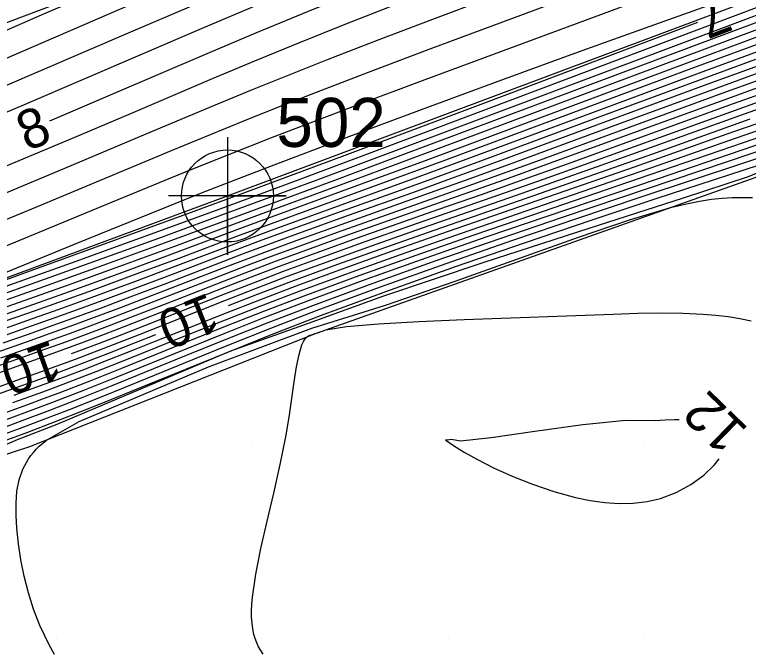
# Model space of a CAD drawing. Extents: x 2602990 to 2605851, y 618069 to 619180.
# Drawn here: x 2603377.87 to 2603415.29, y 618389.19 to 618421.79 of the extents above; entities that cross this region are included whole.
import ezdxf

# ---------------------------------------------------------------- set-up
doc = ezdxf.new("R2010")
doc.units = 0
for name, color, linetype in [('DTM Contours Major', 7, 'Continuous'), ('DTM Contours Major Text', 7, 'Continuous'), ('DTM Contours Minor', 7, 'Continuous'), ('DTM Contours Minor Text', 7, 'Continuous'), ('Exist DTM Breakline', 7, 'Continuous'), ('Exist DTM Crownline', 7, 'Continuous'), ('Exist DTM Drainline', 7, 'Continuous'), ('Exist DTM Drainline Cogo Number', 7, 'Continuous'), ('Exist DTM Drainline Cogo Point CELL', 7, 'Continuous'), ('Exist DTM QL2 LIDAR Elevation Point', 7, 'Continuous'), ('Exist Roads EOP', 7, 'Continuous'), ('PH Exist DTM Breakline', 7, 'Continuous')]:
    doc.layers.add(name, color=color, linetype=linetype)

# ---------------------------------------------------------------- blocks, each defined once
blk = doc.blocks.new('EXIST DTM DRAINLINE COGO POINT')
at = {"layer": 'Exist DTM Drainline Cogo Point CELL'}
blk.add_lwpolyline([(0, 0.06), (0, -0.06), (0, 0), (0.06, 0), (-0.06, 0)], dxfattribs=at)
blk.add_circle((0, 0), 0.04688, dxfattribs=at)

msp = doc.modelspace()

# ---------------------------------------------------------------- linework, layer by layer
at = {"layer": 'DTM Contours Major'}
for points in [[(2603413.545, 618431.919), (2603412.996, 618431.681), (2603409.631, 618430.243), (2603406.411, 618428.892), (2603404.635, 618428.163), (2603402.929, 618427.472), (2603397.939, 618425.471), (2603396.224, 618424.775), (2603393.341, 618423.584), (2603390.362, 618422.333), (2603387.382, 618421.067), (2603378.36, 618417.204), (2603374.888, 618415.735), (2603371.983, 618414.523), (2603369.421, 618413.467), (2603366.184, 618412.15), (2603362.493, 618410.666), (2603360.498, 618409.871), (2603355.313, 618407.823), (2603347.349, 618404.69), (2603343.063, 618402.99), (2603334.617, 618399.609), (2603327.541, 618396.809), (2603322.626, 618394.861)], [(2603377.465, 618406.199), (2603378.885, 618406.7), (2603381.649, 618407.69), (2603384.266, 618408.647), (2603386.257, 618409.391), (2603389.209, 618410.503), (2603390.976, 618411.156), (2603397.03, 618413.357), (2603399.859, 618414.399), (2603412.516, 618419.101), (2603416.414, 618420.536)], [(2603388.785, 618406.968), (2603390.263, 618407.544), (2603392.004, 618408.206), (2603394.355, 618409.072), (2603396.811, 618409.95), (2603399.327, 618410.832), (2603404.362, 618412.578), (2603406.793, 618413.425), (2603410.417, 618414.707), (2603415.392, 618416.478)], [(2603393.201, 618405.543), (2603393.274, 618405.56), (2603393.614, 618405.688), (2603393.745, 618405.726), (2603394.797, 618405.893), (2603396.431, 618406.032), (2603398.488, 618406.149), (2603400.806, 618406.251), (2603408.396, 618406.538), (2603409.666, 618406.576), (2603410.851, 618406.593), (2603411.953, 618406.583), (2603412.976, 618406.538), (2603413.637, 618406.484), (2603414.266, 618406.408), (2603414.867, 618406.31), (2603415.444, 618406.189)], [(2603376.889, 618402.417), (2603377.898, 618402.77), (2603378.871, 618403.116), (2603379.819, 618403.461), (2603380.753, 618403.808), (2603381.684, 618404.16), (2603382.624, 618404.523), (2603384.037, 618405.079), (2603385.068, 618405.49)], [(2603390.549, 618389.192), (2603390.426, 618389.382), (2603390.317, 618389.578), (2603390.223, 618389.781), (2603390.144, 618389.991), (2603390.079, 618390.209), (2603390.019, 618390.487), (2603389.98, 618390.779), (2603389.96, 618391.086), (2603389.957, 618391.408), (2603389.971, 618391.746), (2603390, 618392.102), (2603390.167, 618393.279), (2603390.427, 618394.582), (2603390.746, 618395.973), (2603391.089, 618397.412), (2603391.422, 618398.861), (2603391.71, 618400.279), (2603391.878, 618401.281), (2603392.016, 618402.224), (2603392.138, 618403.086), (2603392.255, 618403.846), (2603392.38, 618404.482), (2603392.528, 618404.972), (2603392.567, 618405.063), (2603392.608, 618405.145), (2603392.652, 618405.218), (2603392.698, 618405.28), (2603392.748, 618405.333), (2603392.801, 618405.375), (2603392.865, 618405.42), (2603392.933, 618405.453), (2603393.072, 618405.499), (2603393.201, 618405.543)]]:
    msp.add_lwpolyline(points, dxfattribs=at)
at = {"layer": 'DTM Contours Minor'}
for points in [[(2603415.971, 618436.239), (2603414.184, 618435.441), (2603412.408, 618434.669), (2603410.673, 618433.922), (2603409.232, 618433.298), (2603401.988, 618430.14), (2603383.339, 618422.102), (2603375.419, 618418.701), (2603372.067, 618417.276), (2603370.458, 618416.602), (2603368.309, 618415.722), (2603367.778, 618415.509)], [(2603403.118, 618431.883), (2603402.833, 618431.716), (2603401.509, 618431.051), (2603400.138, 618430.437), (2603398.705, 618429.837), (2603396.601, 618428.974), (2603389.756, 618426.194), (2603387.413, 618425.235), (2603385.098, 618424.275), (2603383.059, 618423.417), (2603381.096, 618422.58), (2603379.234, 618421.777), (2603375.917, 618420.331), (2603372.342, 618418.768), (2603370.744, 618418.086), (2603369.125, 618417.415), (2603367.476, 618416.749), (2603366.161, 618416.225), (2603363.212, 618415.062), (2603355.846, 618412.179), (2603342.883, 618407.119), (2603323.073, 618399.352)], [(2603420.925, 618431.813), (2603413.975, 618428.875), (2603411.497, 618427.843), (2603408.988, 618426.821), (2603406.566, 618425.862), (2603404.148, 618424.925), (2603399.344, 618423.088), (2603396.97, 618422.174), (2603394.622, 618421.253), (2603392.343, 618420.337), (2603390.114, 618419.421), (2603387.951, 618418.517), (2603383.898, 618416.8), (2603380.805, 618415.486), (2603377.358, 618414.039)], [(2603416.391, 618431.52), (2603413.497, 618430.282), (2603410.574, 618429.047), (2603407.701, 618427.859), (2603405.585, 618427.007), (2603403.524, 618426.193), (2603397.47, 618423.827), (2603395.427, 618423.014), (2603392.846, 618421.963), (2603390.247, 618420.883), (2603387.683, 618419.802), (2603382.87, 618417.749), (2603379.648, 618416.374)], [(2603404.805, 618429.792), (2603402.356, 618428.763), (2603397.015, 618426.54), (2603393.763, 618425.171), (2603390.363, 618423.726), (2603383.658, 618420.855), (2603377.118, 618418.051), (2603373.608, 618416.562), (2603370.947, 618415.449), (2603368.133, 618414.295), (2603365.49, 618413.229), (2603362.398, 618411.996), (2603356.695, 618409.75), (2603347.476, 618406.133), (2603343.027, 618404.375), (2603335.553, 618401.401), (2603324.512, 618397.047), (2603321.717, 618395.941)], [(2603420.115, 618429.811), (2603414.444, 618427.466), (2603412.4, 618426.631), (2603410.273, 618425.78), (2603407.575, 618424.729), (2603404.796, 618423.669), (2603399.182, 618421.553), (2603396.445, 618420.513), (2603393.816, 618419.495), (2603391.861, 618418.719), (2603389.996, 618417.962), (2603388.217, 618417.228), (2603384.894, 618415.834), (2603380.738, 618414.085), (2603376.915, 618412.495), (2603372.47, 618410.663), (2603366.926, 618408.396), (2603360.741, 618405.884), (2603357.67, 618404.644), (2603353.114, 618402.816), (2603345.544, 618399.793), (2603340.999, 618397.957), (2603339.355, 618397.29)], [(2603419.344, 618427.828), (2603414.878, 618426.042), (2603413.257, 618425.399), (2603411.538, 618424.727), (2603408.592, 618423.6), (2603405.452, 618422.42), (2603399.003, 618420.016), (2603395.902, 618418.85), (2603393.023, 618417.746), (2603391.418, 618417.117), (2603389.917, 618416.517), (2603388.501, 618415.943), (2603385.862, 618414.853), (2603379.015, 618412.007), (2603373.646, 618409.794), (2603366.67, 618406.942), (2603359.531, 618404.041), (2603352.87, 618401.348), (2603345.847, 618398.525), (2603340.928, 618396.532), (2603333.274, 618393.41), (2603325.868, 618390.375), (2603313.612, 618385.304)], [(2603417.517, 618425.453), (2603414.066, 618424.14), (2603412.789, 618423.658), (2603409.595, 618422.466), (2603398.796, 618418.475), (2603395.337, 618417.183), (2603392.219, 618416), (2603391, 618415.528), (2603388.789, 618414.656), (2603386.781, 618413.846), (2603382.843, 618412.232), (2603374.157, 618408.651), (2603367.059, 618405.748), (2603358.865, 618402.415), (2603348.621, 618398.269), (2603338.121, 618394.025), (2603335.008, 618392.758), (2603332.478, 618391.718), (2603330.78, 618391.004), (2603330.166, 618390.713), (2603330.794, 618390.91), (2603332.502, 618391.528), (2603335.058, 618392.477), (2603340.472, 618394.503)], [(2603342.346, 618395.203), (2603346.74, 618396.847), (2603349.221, 618397.769), (2603353.79, 618399.451), (2603358.304, 618401.098), (2603362.673, 618402.68), (2603366.805, 618404.166), (2603373.987, 618406.733), (2603380.77, 618409.151), (2603385.418, 618410.826), (2603388.674, 618412.017), (2603392.382, 618413.39), (2603399.188, 618415.936), (2603411.378, 618420.524), (2603420.72, 618424.055)], [(2603290.205, 618375.323), (2603291.172, 618375.7), (2603294.664, 618377.053), (2603299.329, 618378.84), (2603301.718, 618379.745), (2603305.614, 618381.208), (2603309.652, 618382.713), (2603313.719, 618384.22), (2603329.659, 618390.101), (2603334.868, 618392.036), (2603342.845, 618395.018), (2603349.595, 618397.548), (2603354.049, 618399.193), (2603357.917, 618400.605), (2603361.91, 618402.052), (2603365.862, 618403.476), (2603369.608, 618404.82), (2603380.777, 618408.802), (2603385.235, 618410.41), (2603388.763, 618411.704), (2603393.297, 618413.38), (2603399.856, 618415.829), (2603421.294, 618423.877)], [(2603372.825, 618406.789), (2603380.927, 618410.103), (2603382.815, 618410.87), (2603384.744, 618411.647), (2603387.406, 618412.706), (2603389.571, 618413.553), (2603391.107, 618414.144), (2603394.692, 618415.5), (2603398.618, 618416.96), (2603402.718, 618418.467), (2603406.825, 618419.962), (2603410.772, 618421.387), (2603416.399, 618423.403)], [(2603313.054, 618383.538), (2603329.838, 618389.732), (2603334.678, 618391.531), (2603339.689, 618393.409), (2603342.171, 618394.347), (2603346.586, 618396.033), (2603349.67, 618397.21), (2603350.771, 618397.626), (2603354.149, 618398.885), (2603357.825, 618400.235), (2603361.637, 618401.621), (2603365.425, 618402.986), (2603369.026, 618404.275), (2603374.166, 618406.1), (2603379.131, 618407.858), (2603382.195, 618408.957), (2603385.008, 618409.977), (2603388.356, 618411.209), (2603394.207, 618413.366), (2603397.184, 618414.473), (2603415.908, 618421.475)], [(2603315.864, 618384.142), (2603329.882, 618389.314), (2603334.484, 618391.024), (2603336.858, 618391.914), (2603339.233, 618392.811), (2603341.576, 618393.703), (2603343.851, 618394.58), (2603348.482, 618396.388), (2603350.993, 618397.355), (2603354.232, 618398.574), (2603357.751, 618399.874), (2603361.4, 618401.203), (2603365.029, 618402.512), (2603368.489, 618403.748), (2603372.728, 618405.247), (2603377.537, 618406.937), (2603380.566, 618408.015), (2603383.427, 618409.047), (2603386.036, 618410.004), (2603390.363, 618411.608), (2603395.133, 618413.359), (2603398.065, 618414.445), (2603411.959, 618419.632), (2603416.921, 618421.474)], [(2603412.707, 618421.402), (2603411.625, 618420.99), (2603403.095, 618417.762), (2603398.85, 618416.164), (2603394.846, 618414.662), (2603389.592, 618412.707), (2603387.006, 618411.755), (2603383.137, 618410.345), (2603372.741, 618406.586)], [(2603365.859, 618402.474), (2603367.975, 618403.229), (2603372.223, 618404.725), (2603377.51, 618406.572), (2603380.427, 618407.607), (2603383.205, 618408.611), (2603385.772, 618409.557), (2603389.77, 618411.05), (2603396.075, 618413.356), (2603398.96, 618414.421), (2603412.233, 618419.364), (2603416.234, 618420.844)], [(2603377.41, 618405.823), (2603378.785, 618406.306), (2603380.136, 618406.787), (2603381.46, 618407.264), (2603382.752, 618407.735), (2603384.009, 618408.2), (2603386.055, 618408.968), (2603389.321, 618410.206), (2603391.294, 618410.936), (2603397.993, 618413.361), (2603400.759, 618414.376), (2603406.795, 618416.612), (2603412.803, 618418.838), (2603416.6, 618420.23)], [(2603377.289, 618405.064), (2603378.581, 618405.517), (2603379.845, 618405.966), (2603381.084, 618406.414), (2603382.3, 618406.859), (2603383.493, 618407.303), (2603385.633, 618408.115), (2603388.54, 618409.234), (2603389.541, 618409.614), (2603390.571, 618410.001), (2603391.946, 618410.506), (2603394.905, 618411.57), (2603398.176, 618412.739), (2603399.94, 618413.374), (2603402.552, 618414.326), (2603408.033, 618416.344), (2603413.381, 618418.315), (2603415.827, 618419.206)], [(2603377.351, 618405.444), (2603378.683, 618405.911), (2603379.99, 618406.376), (2603381.271, 618406.838), (2603382.525, 618407.297), (2603383.751, 618407.751), (2603385.847, 618408.543), (2603389.432, 618409.91), (2603390.369, 618410.261), (2603391.617, 618410.719), (2603394.31, 618411.691), (2603397.32, 618412.772), (2603398.964, 618413.367), (2603401.657, 618414.351), (2603407.418, 618416.48), (2603413.092, 618418.577), (2603415.677, 618419.523)], [(2603376.658, 618404.487), (2603377.228, 618404.684), (2603378.48, 618405.122), (2603379.702, 618405.557), (2603380.899, 618405.989), (2603382.075, 618406.421), (2603383.235, 618406.854), (2603384.382, 618407.289), (2603388.556, 618408.902), (2603389.647, 618409.318), (2603390.774, 618409.741), (2603392.279, 618410.295), (2603393.858, 618410.864), (2603399.041, 618412.709), (2603400.919, 618413.383), (2603403.441, 618414.298), (2603408.641, 618416.206), (2603413.67, 618418.053), (2603415.98, 618418.891)], [(2603377.167, 618404.304), (2603378.379, 618404.728), (2603379.561, 618405.148), (2603380.716, 618405.566), (2603381.853, 618405.984), (2603382.977, 618406.405), (2603384.094, 618406.83), (2603388.57, 618408.569), (2603389.752, 618409.022), (2603390.977, 618409.483), (2603392.616, 618410.086), (2603394.335, 618410.705), (2603399.914, 618412.682), (2603401.9, 618413.391), (2603404.325, 618414.268), (2603409.241, 618416.065), (2603413.958, 618417.791), (2603416.137, 618418.578)], [(2603377.107, 618403.925), (2603378.281, 618404.335), (2603379.421, 618404.74), (2603380.535, 618405.144), (2603381.631, 618405.548), (2603382.719, 618405.956), (2603383.805, 618406.371), (2603386.143, 618407.283), (2603388.58, 618408.236), (2603389.855, 618408.726), (2603391.181, 618409.226), (2603392.957, 618409.879), (2603394.818, 618410.548), (2603400.794, 618412.658), (2603402.882, 618413.4), (2603405.203, 618414.235), (2603409.833, 618415.921), (2603414.246, 618417.529), (2603416.296, 618418.266)], [(2603364.716, 618399.36), (2603366.269, 618399.898), (2603368.207, 618400.558), (2603375.42, 618402.987), (2603377.05, 618403.546), (2603378.184, 618403.942), (2603379.282, 618404.333), (2603380.355, 618404.722), (2603381.411, 618405.112), (2603382.461, 618405.507), (2603383.513, 618405.91), (2603385.985, 618406.879), (2603388.588, 618407.901), (2603389.958, 618408.43), (2603391.385, 618408.97), (2603393.302, 618409.675), (2603395.308, 618410.395), (2603399.515, 618411.876), (2603401.68, 618412.636), (2603403.863, 618413.408), (2603406.074, 618414.2), (2603414.533, 618417.266), (2603416.457, 618417.954)], [(2603376.942, 618402.792), (2603377.993, 618403.16), (2603379.008, 618403.521), (2603379.998, 618403.881), (2603380.973, 618404.242), (2603381.945, 618404.609), (2603382.923, 618404.986), (2603384.272, 618405.516), (2603388.599, 618407.232), (2603390.161, 618407.839), (2603391.796, 618408.46), (2603394.001, 618409.271), (2603396.305, 618410.096), (2603398.674, 618410.928), (2603403.465, 618412.596), (2603405.82, 618413.421), (2603407.792, 618414.12), (2603415.106, 618416.741), (2603416.782, 618417.333)], [(2603380.765, 618404.519), (2603381.192, 618404.677), (2603382.203, 618405.058), (2603383.219, 618405.449), (2603384.506, 618405.952), (2603388.594, 618407.567), (2603390.059, 618408.135), (2603391.59, 618408.715), (2603393.65, 618409.472), (2603395.804, 618410.244), (2603398.026, 618411.027), (2603402.571, 618412.615), (2603404.843, 618413.415), (2603406.937, 618414.161), (2603414.819, 618417.003), (2603416.619, 618417.643)], [(2603417.111, 618416.714), (2603414.206, 618415.697), (2603409.476, 618414.026), (2603407.762, 618413.427), (2603399.983, 618410.738), (2603397.319, 618409.805), (2603394.71, 618408.873), (2603392.21, 618407.953), (2603390.362, 618407.248), (2603388.606, 618406.561), (2603385.333, 618405.254), (2603383.8, 618404.64), (2603382.323, 618404.058), (2603381.428, 618403.712), (2603380.54, 618403.376), (2603379.651, 618403.046), (2603378.749, 618402.718), (2603377.824, 618402.388)], [(2603417.276, 618416.405), (2603414.62, 618415.484), (2603410.303, 618413.974), (2603408.726, 618413.426), (2603400.642, 618410.646), (2603397.829, 618409.663), (2603395.066, 618408.676), (2603392.417, 618407.701), (2603390.462, 618406.954), (2603388.609, 618406.227), (2603386.846, 618405.523), (2603383.561, 618404.202), (2603382.02, 618403.592), (2603381.171, 618403.263), (2603380.33, 618402.943), (2603379.488, 618402.629), (2603378.634, 618402.317), (2603377.758, 618402.003)], [(2603417.438, 618416.096), (2603415.028, 618415.269), (2603409.683, 618413.423), (2603404.229, 618411.561), (2603401.3, 618410.554), (2603398.339, 618409.522), (2603395.421, 618408.481), (2603392.623, 618407.45), (2603390.562, 618406.661), (2603388.611, 618405.893), (2603386.761, 618405.151), (2603383.321, 618403.761), (2603381.713, 618403.121), (2603380.124, 618402.507), (2603379.332, 618402.209), (2603378.529, 618401.913), (2603376.861, 618401.313)], [(2603417.598, 618415.787), (2603414.311, 618414.671), (2603410.637, 618413.417), (2603405.019, 618411.511), (2603401.96, 618410.465), (2603398.853, 618409.383), (2603395.784, 618408.289), (2603392.84, 618407.203), (2603390.676, 618406.373), (2603388.63, 618405.565), (2603386.69, 618404.784), (2603383.08, 618403.319), (2603381.386, 618402.643), (2603379.891, 618402.063), (2603378.385, 618401.497), (2603376.811, 618400.926)], [(2603416.787, 618415.155), (2603408.825, 618412.48), (2603405.801, 618411.46), (2603402.614, 618410.373), (2603399.362, 618409.243), (2603396.145, 618408.096), (2603393.059, 618406.956), (2603390.793, 618406.085), (2603388.653, 618405.237), (2603386.623, 618404.416), (2603382.832, 618402.873), (2603381.04, 618402.157), (2603379.651, 618401.618), (2603378.248, 618401.09), (2603376.787, 618400.557)], [(2603419.649, 618415.359), (2603413.548, 618413.374), (2603410.584, 618412.403), (2603407.32, 618411.321), (2603403.867, 618410.156), (2603400.338, 618408.937), (2603396.845, 618407.693), (2603393.501, 618406.454), (2603391.049, 618405.506), (2603388.729, 618404.579), (2603384.367, 618402.802), (2603382.27, 618401.954), (2603380.19, 618401.136), (2603378.521, 618400.504), (2603376.792, 618399.874)], [(2603417, 618414.866), (2603412.539, 618413.395), (2603409.707, 618412.454), (2603406.579, 618411.407), (2603403.264, 618410.28), (2603399.871, 618409.103), (2603396.509, 618407.904), (2603393.285, 618406.71), (2603390.922, 618405.798), (2603388.688, 618404.91), (2603386.566, 618404.049), (2603382.57, 618402.421), (2603380.656, 618401.66), (2603379.391, 618401.171), (2603378.108, 618400.69), (2603376.778, 618400.204)], [(2603361.959, 618394.628), (2603367.467, 618396.399), (2603370.576, 618397.419), (2603373.523, 618398.424), (2603376.109, 618399.364), (2603377.109, 618399.757), (2603378.02, 618400.135), (2603380.042, 618400.929), (2603388.894, 618404.654), (2603392.864, 618406.072), (2603396.7, 618407.462), (2603401.773, 618409.161), (2603407.171, 618410.913), (2603411.982, 618412.461), (2603415.295, 618413.548), (2603416.198, 618413.918)], [(2603393.032, 618405.808), (2603396.783, 618406.994), (2603400.341, 618408.208), (2603406.628, 618410.447), (2603409.231, 618411.336), (2603411.389, 618411.98), (2603412.136, 618412.159), (2603412.808, 618412.292), (2603413.413, 618412.385), (2603413.962, 618412.443), (2603414.465, 618412.473), (2603414.932, 618412.481), (2603415.224, 618412.478), (2603415.507, 618412.468)], [(2603379.906, 618389.191), (2603379.636, 618389.677), (2603379.389, 618390.164), (2603379.165, 618390.654), (2603378.839, 618391.487), (2603378.573, 618392.329), (2603378.361, 618393.171), (2603378.197, 618394.007), (2603378.076, 618394.829), (2603377.992, 618395.629), (2603377.95, 618396.275), (2603377.944, 618396.9), (2603377.989, 618397.502), (2603378.101, 618398.08), (2603378.293, 618398.633), (2603378.581, 618399.158), (2603378.698, 618399.323), (2603378.828, 618399.485), (2603378.971, 618399.645), (2603379.13, 618399.802), (2603379.305, 618399.958), (2603379.497, 618400.112), (2603381.158, 618401.062), (2603387.766, 618403.844), (2603393.032, 618405.808)], [(2603411.764, 618401.148), (2603411.524, 618401.145), (2603411.058, 618401.125), (2603410.543, 618401.089), (2603409.054, 618401.112), (2603406.858, 618400.892), (2603404.412, 618400.556), (2603402.176, 618400.232), (2603400.607, 618400.049), (2603400.163, 618400.134)], [(2603400.163, 618400.134), (2603400.03, 618400.121), (2603399.939, 618400.116), (2603399.851, 618400.122), (2603399.842, 618400.125), (2603399.874, 618400.11), (2603400.208, 618399.872), (2603400.573, 618399.635), (2603400.804, 618399.495), (2603401.479, 618399.12), (2603402.305, 618398.705), (2603403.25, 618398.278), (2603404.282, 618397.864), (2603405.369, 618397.492), (2603406.48, 618397.188), (2603407.232, 618397.033), (2603407.977, 618396.928), (2603408.71, 618396.879), (2603409.429, 618396.893), (2603410.13, 618396.975), (2603410.809, 618397.133), (2603411.619, 618397.439), (2603412.364, 618397.844), (2603413.018, 618398.317), (2603413.555, 618398.83), (2603413.807, 618399.164)]]:
    msp.add_lwpolyline(points, dxfattribs=at)
at = {"layer": 'Exist DTM Breakline'}
msp.add_lwpolyline([(2603537.954, 618480.779), (2603486.109, 618461.906), (2603428.704, 618440.722), (2603369.241, 618418.295), (2603303.922, 618394.289), (2603246.763, 618372.687), (2603198.271, 618355.074)], dxfattribs=at)
at = {"layer": 'Exist DTM Crownline'}
msp.add_spline([(2603233.488, 618380.754), (2603285.185, 618400.095), (2603335.457, 618418.629), (2603390.812, 618439.069), (2603440.087, 618457.325), (2603493.996, 618477.231), (2603542.655, 618495.301), (2603600.808, 618516.867), (2603653.659, 618536.362), (2603706.222, 618555.742), (2603764.811, 618577.593), (2603823.52, 618599.847), (2603878.564, 618620.56), (2603937.951, 618643.078), (2603997.369, 618665.789), (2604036.209, 618680.665), (2604055.311, 618688.017)], degree=3, dxfattribs=at)
at = {"layer": 'Exist DTM Drainline'}
msp.add_lwpolyline([(2603204.098, 618342.063), (2603247.886, 618359.31), (2603300.002, 618379.256), (2603348.063, 618397.511), (2603388.725, 618412.554), (2603432.793, 618429.056), (2603474.09, 618444.074), (2603510.151, 618459.891), (2603545.952, 618474.924)], dxfattribs=at)
at = {"layer": 'Exist DTM QL2 LIDAR Elevation Point'}
for p, q in [((2603390, 618400), (2603390, 618400)), ((2603400, 618400), (2603400, 618400)), ((2603410, 618400), (2603410, 618400)), ((2603380, 618390), (2603380, 618390)), ((2603390, 618390), (2603390, 618390)), ((2603400, 618390), (2603400, 618390)), ((2603410, 618390), (2603410, 618390))]:
    msp.add_line(p, q, dxfattribs=at)
at = {"layer": 'Exist Roads EOP'}
for points in [[(2603230.17, 618389.98), (2603282.929, 618409.597), (2603332.773, 618427.868), (2603388.167, 618448.413), (2603437.203, 618466.721), (2603490.778, 618486.527), (2603539.039, 618504.558), (2603597.451, 618526.156), (2603651.053, 618545.972), (2603705.208, 618566.084), (2603762.02, 618587.183), (2603820.334, 618609.162), (2603876.341, 618629.99), (2603934.909, 618652.28), (2603996.409, 618675.568), (2604033.216, 618689.957), (2604052.01, 618697.199)], [(2604034.633, 618668.486), (2603984.89, 618650.123), (2603936.767, 618631.654), (2603888.195, 618613.335), (2603837.766, 618594.258), (2603782.918, 618573.705), (2603731.939, 618554.39), (2603671.126, 618532.171), (2603621.822, 618514.106), (2603561.545, 618491.877), (2603506.421, 618471.293), (2603452.163, 618451.33), (2603398.364, 618431.316), (2603341.431, 618410.355), (2603281.65, 618388.199), (2603223.033, 618366.475), (2603185.717, 618352.612)]]:
    msp.add_spline(points, degree=3, dxfattribs=at)
at = {"layer": 'PH Exist DTM Breakline'}
msp.add_lwpolyline([(2603546.278, 618467.89), (2603526.855, 618460.306), (2603507.213, 618451.651), (2603485.725, 618442.619), (2603466.383, 618433.876), (2603454.696, 618429.386), (2603442.234, 618424.385), (2603428.822, 618418.102), (2603416.965, 618413.956), (2603393.207, 618405.535), (2603378.639, 618399.772), (2603357.505, 618392.883), (2603332.502, 618384.211), (2603305.954, 618375.46), (2603282.242, 618367.811), (2603247.909, 618354.209), (2603229.683, 618345.761), (2603219.668, 618341.177), (2603212.41, 618339.282), (2603206.143, 618338.068)], dxfattribs=at)

# ---------------------------------------------------------------- block references
at = {"layer": 'Exist DTM Drainline Cogo Point CELL', "xscale": 50, "yscale": 50}
msp.add_blockref('EXIST DTM DRAINLINE COGO POINT', (2603388.725, 618412.554), dxfattribs=at)
msp.add_blockref('EXIST DTM DRAINLINE COGO POINT', (2603388.725, 618412.554), dxfattribs=at)

# ---------------------------------------------------------------- texts
at = {"layer": 'DTM Contours Major Text'}
msp.add_text('10', height=2, rotation=201.6812, dxfattribs=at).set_placement((2603387.763, 618407.641))
at = {"layer": 'DTM Contours Minor Text'}
for s, rotation, p in [('7', 200.8436, (2603413.897, 618422.925)), ('8', 22.8757, (2603378.513, 618414.809)), ('10', 199.7081, (2603379.772, 618405.214)), ('12', 135.8403, (2603415.354, 618400.666))]:
    msp.add_text(s, height=2, rotation=rotation, dxfattribs=at).set_placement(p)
at = {"layer": 'Exist DTM Drainline Cogo Number'}
msp.add_text('502', height=2.5, dxfattribs=at).set_placement((2603391.225, 618415.054))

doc.saveas('drawing.dxf')
